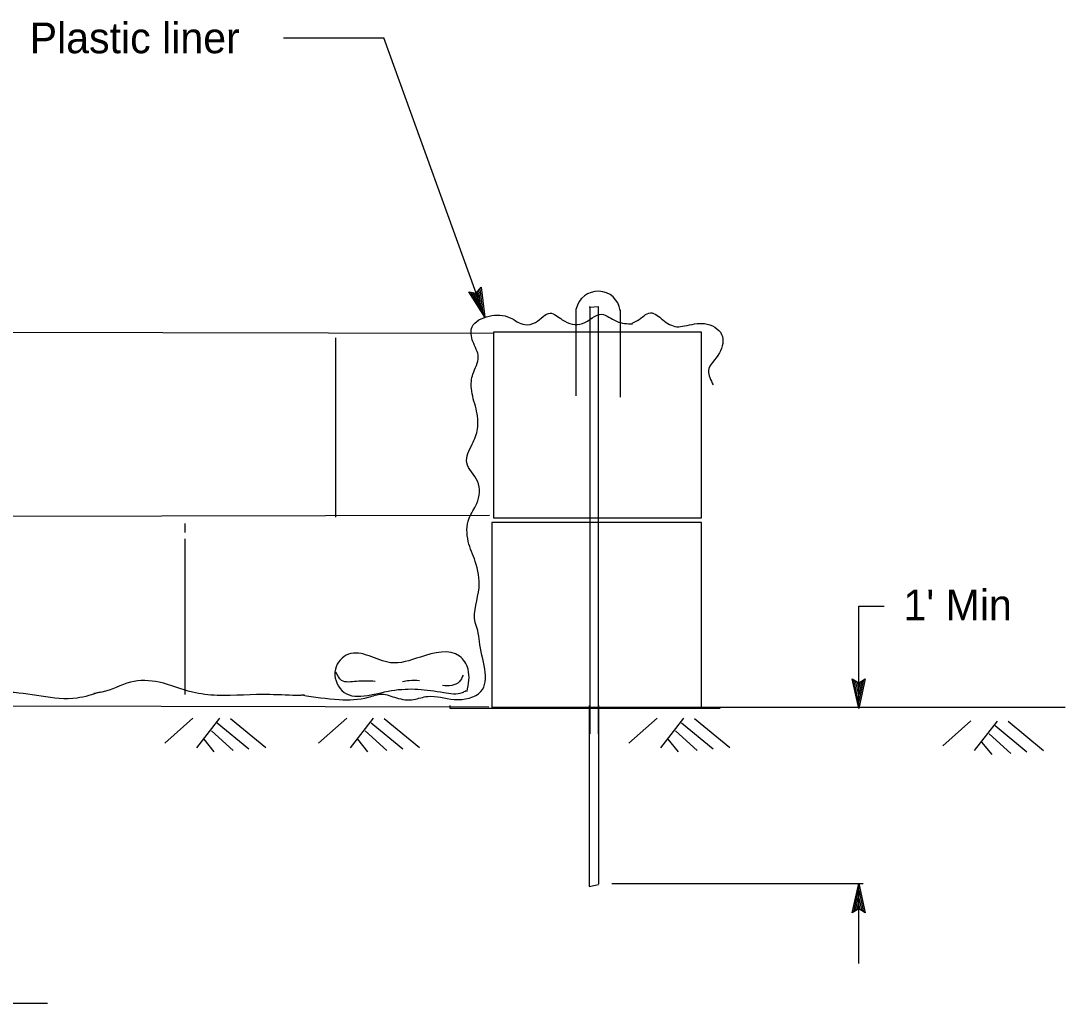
# Model space of a CAD drawing. Extents: x 6708826 to 6711089, y 1868571 to 1869537.
# Drawn here: x 6709714.7 to 6709918.6, y 1869091.6 to 1869283.4 of the extents above; entities that cross this region are included whole.
import ezdxf

# ---------------------------------------------------------------- set-up
doc = ezdxf.new("R2010")
doc.units = 0
for name, color, linetype in [('56 Stg 3 Anno', 7, 'Continuous'), ('57 Undefined', 7, 'Continuous'), ('59 Soundwall Ann', 7, 'Continuous'), ('60 Nongeo Data', 7, 'Continuous')]:
    doc.layers.add(name, color=color, linetype=linetype)

msp = doc.modelspace()

# ---------------------------------------------------------------- linework, layer by layer
at = {"layer": '56 Stg 3 Anno'}
for p, q in [((6709765.94, 1869280.08), (6709785.57, 1869280.08)), ((6709805.29, 1869225.52), (6709785.57, 1869280.08)), ((6709805.29, 1869225.52), (6709802.13, 1869230.5)), ((6709802.13, 1869230.5), (6709802.13, 1869230.5)), ((6709802.13, 1869230.5), (6709803.59, 1869230.21)), ((6709804.83, 1869226.77), (6709802.53, 1869230.41)), ((6709804.39, 1869228.01), (6709802.9, 1869230.36)), ((6709803.94, 1869229.26), (6709803.3, 1869230.27)), ((6709803.59, 1869230.21), (6709804.54, 1869231.37)), ((6709803.79, 1869230.46), (6709803.94, 1869229.26)), ((6709804.04, 1869230.73), (6709804.39, 1869228.01)), ((6709804.29, 1869231.06), (6709804.84, 1869226.77)), ((6709804.54, 1869231.37), (6709804.54, 1869231.37)), ((6709804.54, 1869231.37), (6709805.29, 1869225.52)), ((6709805.29, 1869225.52), (6709805.29, 1869225.52)), ((6709878.28, 1869169.1), (6709883.25, 1869169.1)), ((6709878.28, 1869149.12), (6709878.28, 1869169.1)), ((6709878.28, 1869149.12), (6709877, 1869154.88)), ((6709877, 1869154.88), (6709877, 1869154.88)), ((6709877, 1869154.88), (6709878.28, 1869154.11)), ((6709878.27, 1869150.46), (6709877.34, 1869154.66)), ((6709878.28, 1869151.77), (6709877.68, 1869154.49)), ((6709878.28, 1869153.1), (6709878.02, 1869154.26)), ((6709878.28, 1869154.11), (6709879.56, 1869154.88)), ((6709879.56, 1869154.88), (6709878.28, 1869149.12)), ((6709879.22, 1869154.67), (6709878.28, 1869150.45)), ((6709878.88, 1869154.45), (6709878.28, 1869151.77)), ((6709878.54, 1869154.28), (6709878.28, 1869153.1)), ((6709879.56, 1869154.88), (6709879.56, 1869154.88)), ((6709878.28, 1869149.12), (6709878.28, 1869149.12)), ((6709830.05, 1869114.95), (6709879.14, 1869114.95)), ((6709876.99, 1869109.19), (6709878.28, 1869114.95)), ((6709877.33, 1869109.4), (6709878.27, 1869113.63)), ((6709878.28, 1869114.95), (6709878.28, 1869114.95)), ((6709878.28, 1869114.95), (6709879.55, 1869109.19)), ((6709878.28, 1869099.27), (6709878.28, 1869114.95)), ((6709878.28, 1869113.61), (6709879.21, 1869109.42)), ((6709877.68, 1869109.62), (6709878.27, 1869112.3)), ((6709878.27, 1869112.3), (6709878.87, 1869109.59)), ((6709878.28, 1869109.96), (6709876.99, 1869109.19)), ((6709878.01, 1869109.79), (6709878.27, 1869110.97)), ((6709878.27, 1869110.97), (6709878.53, 1869109.81)), ((6709879.55, 1869109.19), (6709878.28, 1869109.96)), ((6709876.99, 1869109.19), (6709876.99, 1869109.19)), ((6709879.55, 1869109.19), (6709879.55, 1869109.19))]:
    msp.add_line(p, q, dxfattribs=at)
at = {"layer": '57 Undefined'}
msp.add_line((6709625.91, 1869091.56), (6709719.89, 1869091.56), dxfattribs=at)
at = {"layer": '59 Soundwall Ann'}
for p, q in [((6709748.28, 1869147.22), (6709742.8, 1869142.35)), ((6709753.47, 1869147.19), (6709748.95, 1869141.44)), ((6709753.03, 1869146.33), (6709759.22, 1869141.23)), ((6709755.58, 1869147.17), (6709762.5, 1869141.47)), ((6709778.3, 1869147.22), (6709772.82, 1869142.35)), ((6709783.49, 1869147.19), (6709778.97, 1869141.44)), ((6709783.05, 1869146.33), (6709789.23, 1869141.23)), ((6709785.6, 1869147.17), (6709792.52, 1869141.47)), ((6709838.9, 1869147.22), (6709833.42, 1869142.35)), ((6709844.09, 1869147.19), (6709839.58, 1869141.44)), ((6709843.65, 1869146.33), (6709849.84, 1869141.23)), ((6709846.2, 1869147.17), (6709853.13, 1869141.47)), ((6709900.15, 1869146.66), (6709894.68, 1869141.78)), ((6709905.35, 1869146.62), (6709900.83, 1869140.87)), ((6709907.46, 1869146.6), (6709914.38, 1869140.9)), ((6709751.89, 1869144.74), (6709756.12, 1869140.89)), ((6709781.91, 1869144.74), (6709786.14, 1869140.89)), ((6709842.52, 1869144.74), (6709846.75, 1869140.89)), ((6709903.77, 1869144.17), (6709908, 1869140.32)), ((6709904.9, 1869145.76), (6709911.09, 1869140.66)), ((6709750.39, 1869143.09), (6709752.37, 1869140.66)), ((6709780.41, 1869143.09), (6709782.39, 1869140.66)), ((6709841.02, 1869143.09), (6709843, 1869140.66)), ((6709902.27, 1869142.52), (6709904.25, 1869140.09))]:
    msp.add_line(p, q, dxfattribs=at)
at = {"layer": '60 Nongeo Data'}
for p, q in [((6709823.86, 1869229.14), (6709823.86, 1869229.14)), ((6709823.11, 1869210.18), (6709823.11, 1869227.18)), ((6709825.8, 1869227.4), (6709825.8, 1869227.63)), ((6709825.8, 1869227.51), (6709827.42, 1869227.63)), ((6709825.8, 1869227.4), (6709825.8, 1869144.14)), ((6709827.42, 1869227.63), (6709827.42, 1869144.14)), ((6709831.68, 1869226.94), (6709831.68, 1869209.94)), ((6709537.12, 1869222.92), (6709807.06, 1869222.39)), ((6709776.08, 1869221.47), (6709776.08, 1869186.5)), ((6709536.5, 1869186.34), (6709806.17, 1869186.87)), ((6709746.68, 1869185.25), (6709746.68, 1869183.49)), ((6709746.68, 1869182.27), (6709746.68, 1869151.86)), ((6709806.03, 1869149.33), (6709643.26, 1869149.74)), ((6709825.64, 1869149.68), (6709825.64, 1869114.31)), ((6709827.47, 1869149.68), (6709827.47, 1869114.82)), ((6709847.58, 1869149.35), (6709918.59, 1869149.35)), ((6709827.47, 1869114.64), (6709825.64, 1869114.28))]:
    msp.add_line(p, q, dxfattribs=at)
for points in [[(6709847.58, 1869222.59), (6709806.95, 1869222.59), (6709806.95, 1869186.34), (6709847.58, 1869186.34)], [(6709847.58, 1869185.4), (6709806.64, 1869185.4), (6709806.64, 1869149.35), (6709847.58, 1869149.35)]]:
    msp.add_lwpolyline(points, close=True, dxfattribs=at)
msp.add_lwpolyline([(6709798.43, 1869149.68), (6709798.43, 1869149.17), (6709851.25, 1869149.17)], dxfattribs=at)
msp.add_arc((6709827.39, 1869226.24), 4.36, 7.9278, 167.9284, dxfattribs=at)
for points in [[(6709769.53, 1869151.74), (6709776.83, 1869150.85), (6709782.56, 1869151.3), (6709785.13, 1869151.9), (6709788.01, 1869151.17), (6709791.37, 1869150.86), (6709794.12, 1869151.47), (6709799.31, 1869150.86), (6709804.51, 1869152.39), (6709804.2, 1869162.17), (6709803.89, 1869164.31), (6709803.4, 1869165.91), (6709804.15, 1869172.69), (6709803.4, 1869177.82), (6709802.04, 1869181.73), (6709802.19, 1869186.25), (6709803.7, 1869189.12), (6709803.85, 1869193.49), (6709801.74, 1869197.1), (6709802.79, 1869200.72), (6709803.85, 1869203.73), (6709803.55, 1869207.65), (6709802.64, 1869211.57), (6709802.94, 1869214.43), (6709804, 1869217.74), (6709802.94, 1869220.76), (6709802.79, 1869223.62), (6709806.12, 1869225.73), (6709810.19, 1869225.43), (6709813.06, 1869224.07), (6709815.17, 1869224.52), (6709818.04, 1869226.33), (6709820.4, 1869225.03), (6709824.32, 1869224.28), (6709828.1, 1869226.09), (6709830.97, 1869224.73), (6709834.14, 1869224.22)], [(6709834.06, 1869224.39), (6709835.06, 1869224.87), (6709837.63, 1869226.38), (6709840.04, 1869225.02), (6709842.76, 1869223.67), (6709844.27, 1869223.82), (6709848.2, 1869224.27), (6709851.52, 1869222.16), (6709851.07, 1869218.54), (6709848.95, 1869215.07), (6709849.88, 1869212.31)], [(6709801.81, 1869152.4), (6709801.99, 1869156.78), (6709800.35, 1869159.33), (6709792.68, 1869159.15), (6709786.84, 1869158.05), (6709778.63, 1869159.69), (6709776.08, 1869156.78), (6709777.35, 1869152.59), (6709787.03, 1869152.59), (6709797.25, 1869152.22), (6709800.9, 1869152.22), (6709801.63, 1869152.59)], [(6709770.04, 1869151.7), (6709769.31, 1869151.67), (6709763.27, 1869151.82), (6709753, 1869151.67), (6709748.17, 1869152.28), (6709741.68, 1869154.24), (6709736.1, 1869154.24), (6709730.51, 1869152.28), (6709728.95, 1869152.06)], [(6709783.86, 1869154.4), (6709780.21, 1869154.4), (6709777.29, 1869154.58), (6709776.2, 1869156.22)], [(6709792.5, 1869154.52), (6709790.49, 1869154.52), (6709789.22, 1869154.34)], [(6709801.02, 1869155.61), (6709800.29, 1869154.33), (6709798.83, 1869153.6), (6709797, 1869153.6)], [(6709730.16, 1869152.32), (6709725.65, 1869151.13), (6709711.6, 1869152.22), (6709704.48, 1869151.49), (6709688.79, 1869153.86), (6709681.77, 1869152.08)]]:
    msp.add_spline(points, degree=3, dxfattribs=at)

# ---------------------------------------------------------------- texts
at = {"layer": '57 Undefined'}
for s, p in [('Plastic liner', (6709716.39, 1869277.08)), ("1' Min", (6709887.03, 1869166.34))]:
    msp.add_text(s, height=6, dxfattribs=at).set_placement(p)

doc.saveas('drawing.dxf')
